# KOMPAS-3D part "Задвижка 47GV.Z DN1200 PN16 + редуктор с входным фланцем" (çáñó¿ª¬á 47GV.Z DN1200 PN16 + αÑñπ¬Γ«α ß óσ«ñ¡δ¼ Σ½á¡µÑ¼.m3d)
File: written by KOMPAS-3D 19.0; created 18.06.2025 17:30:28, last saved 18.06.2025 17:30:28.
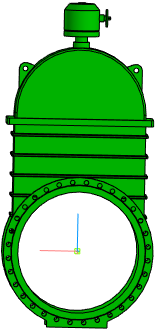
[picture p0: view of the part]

Document properties: Полное имя файла: Задвижка 47GV.Z DN1200 PN16 + редуктор с входным валом.a3d

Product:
- Part/product: Задвижка 47GV.Z DN1200 PN16 + редуктор с входным фланцем
    Масса: 6580.19
  - Body: Тело 1
      Масса: 6582.29

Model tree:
1. Операция без истории:1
